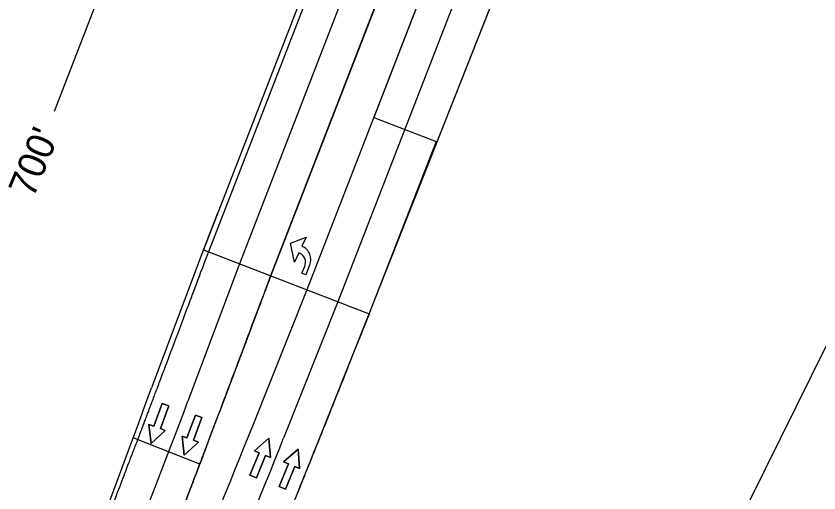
# Model space of a CAD drawing. Extents: x 14104283 to 14129344, y 8637090 to 8673339.
# Drawn here: x 14119793.9 to 14120082.9, y 8670129.3 to 8670301 of the extents above; entities that cross this region are included whole.
import ezdxf

# ---------------------------------------------------------------- set-up
doc = ezdxf.new("R2010")
doc.units = 0
for name, color, linetype in [('Cell', 7, 'Continuous'), ('Default', 7, 'Continuous'), ('dsnNonPlotable', 7, 'Continuous'), ('dsnPaintExistingBrokenLaneLineWhite', 7, 'Continuous'), ('dsnPaintExistingEdgeLineRightWhite', 7, 'Continuous'), ('dsnPaintExistingNoPassingYellow', 7, 'Continuous'), ('dsnPaintExistingStopLineWhite', 7, 'Continuous'), ('dsnShadingPaved', 7, 'Continuous'), ('dsnStdLabel', 7, 'Continuous')]:
    doc.layers.add(name, color=color, linetype=linetype)

msp = doc.modelspace()

# ---------------------------------------------------------------- linework, layer by layer
at = {"layer": 'Cell'}
for p, q in [((14119895.96, 8670215.63), (14119895.67, 8670215.75)), ((14119896.79, 8670218.13), (14119896.96, 8670218.07))]:
    msp.add_line(p, q, dxfattribs=at)
for points in [[(14119892.62, 8670219.28), (14119898.36, 8670221.47), (14119896.79, 8670218.13)], [(14119892.62, 8670219.28), (14119898.36, 8670221.47), (14119896.79, 8670218.13)], [(14119895.67, 8670215.75), (14119894.11, 8670212.42), (14119892.62, 8670219.28)], [(14119895.67, 8670215.75), (14119894.11, 8670212.42), (14119892.62, 8670219.28)], [(14119895.96, 8670215.63), (14119895.67, 8670215.75)], [(14119896.79, 8670218.13), (14119896.96, 8670218.07)], [(14119899.57, 8670211.31), (14119898.18, 8670207.91), (14119896.79, 8670208.47), (14119897.79, 8670210.91)], [(14119899.57, 8670211.31), (14119898.18, 8670207.91), (14119896.79, 8670208.47), (14119897.79, 8670210.91)], [(14119843.46, 8670153.34), (14119841.7, 8670153.99), (14119842.47, 8670147.05), (14119847.57, 8670151.82), (14119845.81, 8670152.47), (14119848.84, 8670160.68), (14119846.5, 8670161.55), (14119843.46, 8670153.34)], [(14119855.39, 8670149.15), (14119853.63, 8670149.8), (14119854.39, 8670142.85), (14119859.49, 8670147.63), (14119857.73, 8670148.28), (14119860.77, 8670156.49), (14119858.42, 8670157.36), (14119855.39, 8670149.15)], [(14119883.7, 8670142.8), (14119885.44, 8670142.09), (14119884.92, 8670149.06), (14119879.66, 8670144.46), (14119881.39, 8670143.75), (14119878.07, 8670135.66), (14119880.38, 8670134.71), (14119883.7, 8670142.8)], [(14119894.22, 8670138.8), (14119895.95, 8670138.08), (14119895.43, 8670145.05), (14119890.17, 8670140.46), (14119891.91, 8670139.74), (14119888.58, 8670131.65), (14119890.9, 8670130.7), (14119894.22, 8670138.8)]]:
    msp.add_lwpolyline(points, dxfattribs=at)
for points in [[(14119846.5, 8670161.55), (14119848.84, 8670160.68), (14119845.81, 8670152.47), (14119847.57, 8670151.82), (14119842.47, 8670147.05), (14119841.7, 8670153.99), (14119843.46, 8670153.34)], [(14119858.42, 8670157.36), (14119860.77, 8670156.49), (14119857.73, 8670148.28), (14119859.49, 8670147.63), (14119854.39, 8670142.85), (14119853.63, 8670149.8), (14119855.39, 8670149.15)], [(14119880.38, 8670134.71), (14119878.07, 8670135.66), (14119881.39, 8670143.75), (14119879.66, 8670144.46), (14119884.92, 8670149.06), (14119885.44, 8670142.09), (14119883.7, 8670142.8)], [(14119890.9, 8670130.7), (14119888.58, 8670131.65), (14119891.91, 8670139.74), (14119890.17, 8670140.46), (14119895.43, 8670145.05), (14119895.95, 8670138.08), (14119894.22, 8670138.8)]]:
    msp.add_lwpolyline(points, close=True, dxfattribs=at)
for centre, major_axis in [((14119894.57, 8670212.23), (-1.4, -3.4)), ((14119894.57, 8670212.23), (-1.4, -3.4)), ((14119894.97, 8670213.2), (-2, -4.86)), ((14119894.97, 8670213.2), (-2, -4.86))]:
    msp.add_ellipse(centre, major_axis=major_axis, ratio=0.9474, start_param=1.570796, end_param=3.141593, dxfattribs=at)
at = {"layer": 'Default'}
msp.add_lwpolyline([(14119861.3, 8670216.88), (14119920.98, 8670193.76), (14120033.72, 8670479.06), (14119972.19, 8670502.91)], close=True, dxfattribs=at)
at = {"layer": 'dsnNonPlotable'}
msp.add_lwpolyline([(14119506.15, 8670149.79), (14120200.88, 8671554.92), (14120653.57, 8671331.1), (14119958.84, 8669925.97)], close=True, dxfattribs=at)
at = {"layer": 'dsnPaintExistingBrokenLaneLineWhite'}
for p, q in [((14119874.41, 8670211.95), (14119985.24, 8670497.85)), ((14119909.84, 8670198.21), (14120020.67, 8670484.12)), ((14119874.36, 8670211.83), (14119855.76, 8670162.36)), ((14119890.24, 8670149.13), (14119909.84, 8670198.21))]:
    msp.add_line(p, q, dxfattribs=at)
for centre, radius, start, end in [((14115417.89, 8671831.2), 4741.27, 336.03045, 339.39146), ((14115455.27, 8671919.94), 4775.43, 334.8735, 338.23249)]:
    msp.add_arc(centre, radius, start, end, dxfattribs=at)
at = {"layer": 'dsnPaintExistingEdgeLineRightWhite'}
for p, q in [((14119920.98, 8670193.76), (14120033.72, 8670479.06)), ((14119866.4, 8670230.03), (14119861.35, 8670217.01)), ((14119861.35, 8670217.01), (14119842.61, 8670167.16)), ((14119901.38, 8670144.67), (14119920.98, 8670193.76))]:
    msp.add_line(p, q, dxfattribs=at)
for centre, radius, start, end in [((14116594.62, 8671342.65), 3454.16, 336.45133, 340.10427), ((14115455.27, 8671919.94), 4787.43, 334.8735, 338.23249)]:
    msp.add_arc(centre, radius, start, end, dxfattribs=at)
at = {"layer": 'dsnPaintExistingNoPassingYellow'}
for p, q in [((14119996.43, 8670493.52), (14119885.6, 8670207.61)), ((14119898.65, 8670202.55), (14120009.48, 8670488.46)), ((14119885.6, 8670207.61), (14119866.99, 8670158.14)), ((14119879.05, 8670153.47), (14119898.65, 8670202.55))]:
    msp.add_line(p, q, dxfattribs=at)
for centre, radius, start, end in [((14115417.89, 8671831.2), 4753.27, 336.03045, 339.39146), ((14115455.27, 8671919.94), 4763.43, 334.8735, 338.23249)]:
    msp.add_arc(centre, radius, start, end, dxfattribs=at)
at = {"layer": 'dsnPaintExistingStopLineWhite'}
msp.add_line((14119859.99, 8670139.64), (14119835.99, 8670149.12), dxfattribs=at)
at = {"layer": 'dsnShadingPaved'}
for points in [[(14119863.22, 8670216.29), (14120042.07, 8670677.65), (14120064.44, 8670668.98), (14119885.6, 8670207.61)], [(14119885.6, 8670207.61), (14120064.44, 8670668.98), (14120077.5, 8670663.92), (14119922.69, 8670264.56), (14119945.07, 8670255.89), (14119945.07, 8670255.89), (14119921.03, 8670193.88)]]:
    msp.add_lwpolyline(points, dxfattribs=at)
for points in [[(14119838.79, 8670151.4), (14119838.85, 8670151.57), (14119838.95, 8670151.82), (14119839.06, 8670152.11), (14119839.11, 8670152.24), (14119839.14, 8670152.32), (14119839.15, 8670152.37), (14119839.23, 8670152.58), (14119839.3, 8670152.74), (14119839.38, 8670152.95), (14119839.39, 8670153), (14119839.42, 8670153.06), (14119839.43, 8670153.08), (14119839.44, 8670153.11), (14119839.44, 8670153.12), (14119839.45, 8670153.14), (14119839.45, 8670153.15), (14119839.49, 8670153.25), (14119839.52, 8670153.33), (14119839.81, 8670154.09), (14119840.06, 8670154.76), (14119840.82, 8670156.77), (14119841.33, 8670158.11), (14119842.34, 8670160.79), (14119842.85, 8670162.13), (14119843.61, 8670164.14), (14119843.86, 8670164.81), (14119844.15, 8670165.57), (14119844.19, 8670165.7), (14119844.25, 8670165.84), (14119844.27, 8670165.91), (14119844.29, 8670165.95), (14119844.3, 8670165.97), (14119844.34, 8670166.07), (14119844.37, 8670166.16), (14119844.43, 8670166.32), (14119844.46, 8670166.41), (14119844.62, 8670166.83), (14119844.75, 8670167.17), (14119846.9, 8670172.9), (14119848.93, 8670178.29), (14119855.02, 8670194.48), (14119859.07, 8670205.27), (14119863.13, 8670216.06)], [(14119861.23, 8670142.88), (14119861.29, 8670143.05), (14119861.35, 8670143.22), (14119861.45, 8670143.47), (14119861.48, 8670143.55), (14119861.52, 8670143.66), (14119861.53, 8670143.68), (14119861.54, 8670143.72), (14119861.55, 8670143.74), (14119861.57, 8670143.78), (14119861.58, 8670143.82), (14119861.59, 8670143.85), (14119861.6, 8670143.87), (14119861.6, 8670143.88), (14119861.64, 8670143.97), (14119861.69, 8670144.1), (14119861.74, 8670144.25), (14119861.77, 8670144.32), (14119861.78, 8670144.35), (14119861.79, 8670144.37), (14119861.8, 8670144.38), (14119861.81, 8670144.42), (14119861.82, 8670144.44), (14119861.83, 8670144.47), (14119861.83, 8670144.49), (14119861.84, 8670144.5), (14119861.84, 8670144.51), (14119861.85, 8670144.52), (14119861.85, 8670144.53), (14119861.86, 8670144.54), (14119861.86, 8670144.56), (14119861.86, 8670144.57), (14119861.87, 8670144.57), (14119861.87, 8670144.58), (14119861.87, 8670144.58), (14119861.87, 8670144.59), (14119861.88, 8670144.6), (14119861.88, 8670144.61), (14119861.88, 8670144.61), (14119861.88, 8670144.61), (14119861.89, 8670144.62), (14119861.89, 8670144.63), (14119861.89, 8670144.64), (14119861.89, 8670144.64), (14119861.89, 8670144.64), (14119861.89, 8670144.65), (14119861.9, 8670144.65), (14119861.9, 8670144.65), (14119861.9, 8670144.65), (14119861.91, 8670144.69), (14119861.93, 8670144.73), (14119861.95, 8670144.8), (14119861.96, 8670144.82), (14119861.98, 8670144.86), (14119861.98, 8670144.88), (14119862.12, 8670145.24), (14119862.25, 8670145.58), (14119862.44, 8670146.08), (14119862.53, 8670146.33), (14119862.65, 8670146.63), (14119862.7, 8670146.77), (14119862.73, 8670146.85), (14119862.74, 8670146.88), (14119862.75, 8670146.9), (14119862.75, 8670146.91), (14119863.27, 8670148.27), (14119863.78, 8670149.62), (14119864.54, 8670151.64), (14119864.92, 8670152.65), (14119865.37, 8670153.83), (14119865.59, 8670154.42), (14119865.7, 8670154.72), (14119865.76, 8670154.86), (14119865.78, 8670154.93), (14119865.8, 8670154.97), (14119865.81, 8670154.99), (14119865.94, 8670155.35), (14119866.13, 8670155.85), (14119866.35, 8670156.44), (14119866.46, 8670156.74), (14119866.52, 8670156.88), (14119866.55, 8670156.96), (14119866.56, 8670156.99), (14119866.57, 8670157.01), (14119866.57, 8670157.02), (14119866.57, 8670157.02), (14119866.61, 8670157.11), (14119866.64, 8670157.2), (14119866.69, 8670157.33), (14119866.7, 8670157.37), (14119866.72, 8670157.42), (14119866.73, 8670157.44), (14119866.73, 8670157.45), (14119866.74, 8670157.46), (14119866.74, 8670157.47), (14119866.75, 8670157.48), (14119866.75, 8670157.49), (14119866.76, 8670157.51), (14119866.76, 8670157.52), (14119866.76, 8670157.53), (14119866.76, 8670157.53), (14119866.77, 8670157.54), (14119866.78, 8670157.58), (14119866.81, 8670157.64), (14119866.83, 8670157.72), (14119866.85, 8670157.75), (14119866.85, 8670157.77), (14119866.86, 8670157.78), (14119866.88, 8670157.83), (14119866.89, 8670157.88), (14119866.92, 8670157.94), (14119866.93, 8670157.96), (14119866.94, 8670158), (14119866.95, 8670158.02), (14119867.08, 8670158.38), (14119867.21, 8670158.72), (14119869.37, 8670164.45), (14119871.39, 8670169.85), (14119877.48, 8670186.03), (14119881.54, 8670196.82), (14119885.6, 8670207.61)], [(14119920.94, 8670193.65), (14119916.66, 8670182.94), (14119912.38, 8670172.22), (14119905.97, 8670156.15), (14119903.83, 8670150.8), (14119901.55, 8670145.11), (14119901.42, 8670144.77), (14119901.27, 8670144.39), (14119901.25, 8670144.35), (14119901.22, 8670144.27), (14119901.2, 8670144.22), (14119901.15, 8670144.1), (14119901.12, 8670144.01), (14119901.08, 8670143.91), (14119901.07, 8670143.89), (14119901.05, 8670143.84), (14119901.02, 8670143.78), (14119900.97, 8670143.63), (14119900.92, 8670143.51), (14119900.61, 8670142.75), (14119900.34, 8670142.08), (14119899.54, 8670140.06), (14119899, 8670138.72), (14119897.92, 8670136.03), (14119897.38, 8670134.68), (14119896.57, 8670132.66), (14119896.3, 8670131.99), (14119895.99, 8670131.24), (14119895.96, 8670131.15), (14119895.92, 8670131.06), (14119895.92, 8670131.06), (14119895.92, 8670131.05), (14119895.91, 8670131.03), (14119895.9, 8670131.02), (14119895.89, 8670130.98), (14119895.88, 8670130.96), (14119895.86, 8670130.9), (14119895.84, 8670130.86), (14119895.76, 8670130.65), (14119895.69, 8670130.48), (14119895.6, 8670130.27), (14119895.59, 8670130.23), (14119895.55, 8670130.15), (14119895.5, 8670130.02), (14119895.38, 8670129.73), (14119895.28, 8670129.48), (14119895.21, 8670129.31)], [(14119813.9, 8670087.31), (14119813.97, 8670087.47), (14119814.06, 8670087.72), (14119814.18, 8670088.01), (14119814.23, 8670088.14), (14119814.26, 8670088.22), (14119814.28, 8670088.26), (14119814.36, 8670088.47), (14119814.43, 8670088.64), (14119814.51, 8670088.85), (14119814.53, 8670088.89), (14119814.55, 8670088.95), (14119814.56, 8670088.97), (14119814.57, 8670089.01), (14119814.58, 8670089.02), (14119814.59, 8670089.04), (14119814.59, 8670089.05), (14119814.63, 8670089.14), (14119814.66, 8670089.22), (14119814.96, 8670089.97), (14119815.22, 8670090.64), (14119816.01, 8670092.64), (14119816.54, 8670093.97), (14119818.11, 8670097.97), (14119821.26, 8670105.96), (14119826.47, 8670119.3), (14119830.6, 8670129.99), (14119833.68, 8670138.01), (14119834.7, 8670140.69), (14119836.24, 8670144.7), (14119836.75, 8670146.04), (14119837.51, 8670148.05), (14119837.77, 8670148.72), (14119838.28, 8670150.06), (14119838.53, 8670150.73), (14119838.79, 8670151.4)], [(14119861.22, 8670142.87), (14119860.96, 8670142.19), (14119860.71, 8670141.52), (14119860.2, 8670140.18), (14119859.94, 8670139.51), (14119859.67, 8670138.79), (14119859.65, 8670138.75), (14119859.62, 8670138.67), (14119859.57, 8670138.54), (14119859.46, 8670138.25), (14119859.24, 8670137.66), (14119858.79, 8670136.48), (14119858.4, 8670135.47), (14119857.12, 8670132.11), (14119856.09, 8670129.42), (14119852.99, 8670121.36), (14119850.92, 8670115.99), (14119846.75, 8670105.25), (14119844.65, 8670099.89), (14119841.5, 8670091.85), (14119840.44, 8670089.17), (14119838.86, 8670085.15), (14119838.33, 8670083.81), (14119837.8, 8670082.46), (14119837.79, 8670082.45), (14119837.78, 8670082.43), (14119837.77, 8670082.4), (14119837.74, 8670082.33), (14119837.68, 8670082.18), (14119837.57, 8670081.89), (14119837.47, 8670081.64), (14119837.27, 8670081.14), (14119837.14, 8670080.8), (14119837, 8670080.45), (14119836.99, 8670080.43), (14119836.97, 8670080.39), (14119836.96, 8670080.36), (14119836.94, 8670080.3), (14119836.92, 8670080.26), (14119836.91, 8670080.22), (14119836.91, 8670080.22), (14119836.91, 8670080.22), (14119836.9, 8670080.21), (14119836.9, 8670080.21), (14119836.9, 8670080.21), (14119836.9, 8670080.2), (14119836.9, 8670080.2), (14119836.9, 8670080.19), (14119836.89, 8670080.18), (14119836.89, 8670080.18), (14119836.89, 8670080.17), (14119836.89, 8670080.17), (14119836.88, 8670080.16), (14119836.88, 8670080.15), (14119836.88, 8670080.15), (14119836.88, 8670080.14), (14119836.87, 8670080.14), (14119836.87, 8670080.13), (14119836.86, 8670080.11), (14119836.86, 8670080.1), (14119836.85, 8670080.09), (14119836.85, 8670080.08), (14119836.85, 8670080.07), (14119836.84, 8670080.05), (14119836.84, 8670080.04), (14119836.82, 8670080.01), (14119836.81, 8670079.99), (14119836.8, 8670079.95), (14119836.8, 8670079.94), (14119836.79, 8670079.92), (14119836.78, 8670079.89), (14119836.75, 8670079.82), (14119836.69, 8670079.67), (14119836.64, 8670079.55), (14119836.6, 8670079.45), (14119836.6, 8670079.44), (14119836.59, 8670079.42), (14119836.58, 8670079.39), (14119836.57, 8670079.36), (14119836.55, 8670079.32), (14119836.54, 8670079.3), (14119836.52, 8670079.25), (14119836.52, 8670079.23), (14119836.47, 8670079.13), (14119836.44, 8670079.05), (14119836.34, 8670078.8), (14119836.28, 8670078.63), (14119836.21, 8670078.46)], [(14119836.21, 8670078.46), (14119836.28, 8670078.63), (14119836.34, 8670078.8), (14119836.44, 8670079.05), (14119836.47, 8670079.13), (14119836.52, 8670079.23), (14119836.52, 8670079.25), (14119836.54, 8670079.3), (14119836.55, 8670079.32), (14119836.57, 8670079.36), (14119836.58, 8670079.39), (14119836.59, 8670079.42), (14119836.6, 8670079.44), (14119836.6, 8670079.45), (14119836.64, 8670079.55), (14119836.69, 8670079.67), (14119836.75, 8670079.82), (14119836.78, 8670079.89), (14119836.79, 8670079.92), (14119836.8, 8670079.94), (14119836.8, 8670079.95), (14119836.81, 8670079.99), (14119836.82, 8670080.01), (14119836.84, 8670080.04), (14119836.84, 8670080.05), (14119836.85, 8670080.07), (14119836.85, 8670080.08), (14119836.85, 8670080.09), (14119836.86, 8670080.1), (14119836.86, 8670080.11), (14119836.87, 8670080.13), (14119836.87, 8670080.14), (14119836.88, 8670080.14), (14119836.88, 8670080.15), (14119836.88, 8670080.15), (14119836.88, 8670080.16), (14119836.89, 8670080.17), (14119836.89, 8670080.17), (14119836.89, 8670080.18), (14119836.89, 8670080.18), (14119836.9, 8670080.19), (14119836.9, 8670080.2), (14119836.9, 8670080.2), (14119836.9, 8670080.21), (14119836.9, 8670080.21), (14119836.9, 8670080.21), (14119836.91, 8670080.22), (14119836.91, 8670080.22), (14119836.91, 8670080.22), (14119836.92, 8670080.26), (14119836.94, 8670080.3), (14119836.96, 8670080.36), (14119836.97, 8670080.39), (14119836.99, 8670080.43), (14119837, 8670080.45), (14119837.14, 8670080.8), (14119837.27, 8670081.14), (14119837.47, 8670081.64), (14119837.57, 8670081.89), (14119837.68, 8670082.18), (14119837.74, 8670082.33), (14119837.77, 8670082.4), (14119837.78, 8670082.43), (14119837.79, 8670082.45), (14119837.8, 8670082.46), (14119838.33, 8670083.81), (14119838.86, 8670085.15), (14119840.44, 8670089.17), (14119841.5, 8670091.85), (14119844.65, 8670099.89), (14119846.75, 8670105.25), (14119850.92, 8670115.99), (14119852.99, 8670121.36), (14119856.09, 8670129.42), (14119857.12, 8670132.11), (14119858.4, 8670135.47), (14119858.79, 8670136.48), (14119859.24, 8670137.66), (14119859.46, 8670138.25), (14119859.57, 8670138.54), (14119859.62, 8670138.67), (14119859.65, 8670138.75), (14119859.67, 8670138.79), (14119859.94, 8670139.51), (14119860.2, 8670140.18), (14119860.71, 8670141.52), (14119860.96, 8670142.19), (14119861.22, 8670142.87)]]:
    msp.add_open_spline(points, degree=3, dxfattribs=at)
msp.add_spline([(14119885.6, 8670207.61), (14119884.94, 8670205.86), (14119884.61, 8670204.98), (14119884.28, 8670204.11), (14119883.95, 8670203.23), (14119883.62, 8670202.36), (14119883.29, 8670201.48), (14119882.96, 8670200.61), (14119882.63, 8670199.73), (14119882.31, 8670198.86), (14119881.98, 8670197.98), (14119881.65, 8670197.11), (14119881.32, 8670196.23), (14119880.99, 8670195.36), (14119880.66, 8670194.48), (14119880.33, 8670193.61), (14119880, 8670192.73), (14119879.67, 8670191.86), (14119879.34, 8670190.98), (14119879.01, 8670190.11), (14119878.68, 8670189.23), (14119878.36, 8670188.36), (14119878.03, 8670187.48), (14119877.7, 8670186.61), (14119877.37, 8670185.73), (14119877.04, 8670184.86), (14119876.71, 8670183.98), (14119876.38, 8670183.1), (14119876.05, 8670182.23), (14119875.72, 8670181.35), (14119875.39, 8670180.48), (14119875.06, 8670179.6), (14119874.74, 8670178.73), (14119874.41, 8670177.85), (14119874.08, 8670176.98), (14119873.75, 8670176.1), (14119873.42, 8670175.23), (14119873.09, 8670174.35), (14119872.76, 8670173.48), (14119872.43, 8670172.6), (14119872.1, 8670171.73), (14119871.77, 8670170.85), (14119871.44, 8670169.98), (14119871.11, 8670169.1), (14119870.79, 8670168.23), (14119870.46, 8670167.35), (14119870.13, 8670166.48), (14119869.8, 8670165.6), (14119869.47, 8670164.73), (14119869.14, 8670163.85), (14119868.81, 8670162.97), (14119868.48, 8670162.1), (14119868.15, 8670161.22), (14119867.82, 8670160.35), (14119867.49, 8670159.47), (14119867.31, 8670158.99)], degree=3, dxfattribs=at)
at = {"layer": 'dsnStdLabel'}
msp.add_line((14119807.69, 8670266.77), (14119908.76, 8670527.51), dxfattribs=at)

# ---------------------------------------------------------------- texts
msp.add_text("700'", height=10, rotation=67.6002, dxfattribs=at).set_placement((14119800.05, 8670235.15))

doc.saveas('drawing.dxf')
